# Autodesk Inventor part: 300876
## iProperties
Created: 2007-12
Part Number: 300876
Document SubType Name: Modeling
Designer: MM
Density: 8.08 g/cm^3
Mass: 81.1085 g
Surface Area: 92.7417 cm^2
Volume: 10.0382 cm^3
Material: Stainless Steel
Description: LEFT SIDE WIRE BAR
Component Category: Back Component
Author: MM
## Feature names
1. TaggingFeature2
